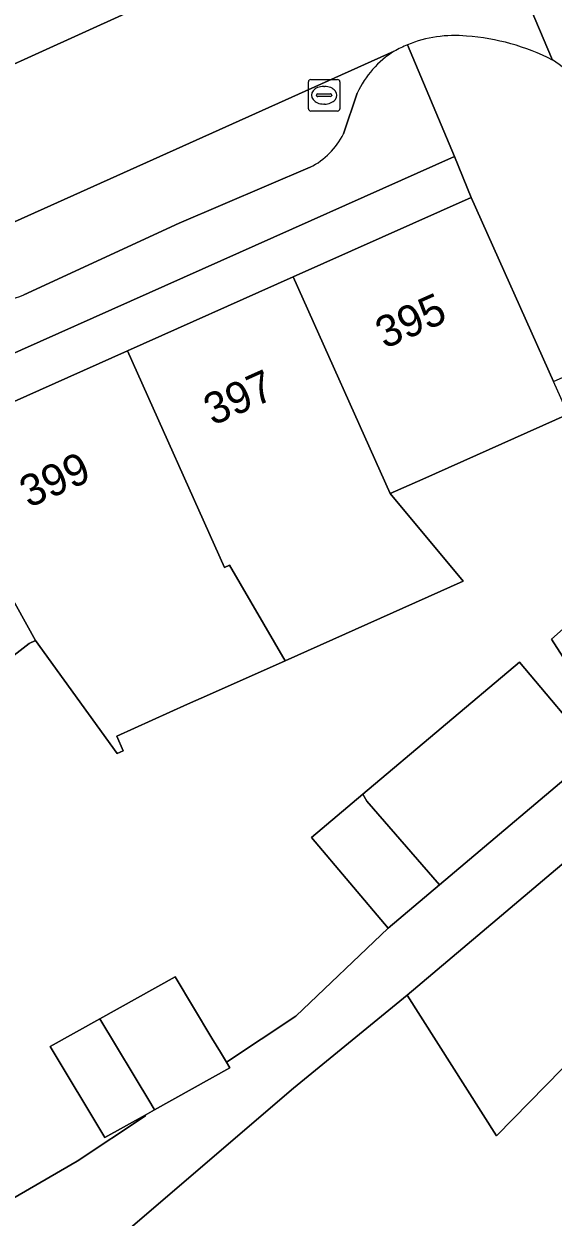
# Model space of a CAD drawing. Extents: x 159217 to 160349, y 381246 to 382172.
# Drawn here: x 159935.86 to 159952.63, y 381548.06 to 381585.9 of the extents above; entities that cross this region are included whole.
import ezdxf

# ---------------------------------------------------------------- set-up
doc = ezdxf.new("R2010")
doc.units = 0
for name, color, linetype in [('IMGEO_Erf', 7, 'Continuous'), ('IMGEO_Kolk', 7, 'Continuous'), ('IMGEO_Pand', 7, 'Continuous'), ('IMGEO_Pand_nummerreeks', 7, 'Continuous'), ('IMGEO_Parkeervlak_open', 7, 'Continuous'), ('IMGEO_Rijbaan_lokaal_open', 7, 'Continuous'), ('IMGEO_Voetpad_open', 7, 'Continuous')]:
    doc.layers.add(name, color=color, linetype=linetype)

msp = doc.modelspace()

# ---------------------------------------------------------------- linework, layer by layer
at = {"layer": 'IMGEO_Erf'}
msp.add_lwpolyline([(159917.626, 381561.413), (159922.162, 381564.929), (159926.698, 381568.444), (159931.35, 381572.05), (159932.725, 381572.665), (159934.053, 381573.258), (159939.145, 381575.534), (159944.394, 381577.88), (159950.038, 381580.402), (159949.504, 381581.701), (159933.502, 381574.549), (159930.356, 381573.305), (159889.378, 381541.471), (159890.288, 381540.224), (159894.945, 381543.834), (159899.482, 381547.35), (159903.996, 381550.849), (159908.553, 381554.381), (159913.09, 381557.897)], close=True, dxfattribs=at)
for points in [[(159953.11, 381573.529), (159948.501, 381571.469), (159947.464, 381571.008), (159949.781, 381568.226), (159944.139, 381565.707), (159941.738, 381564.635), (159941.047, 381564.326), (159938.802, 381563.312), (159939.007, 381562.852), (159938.819, 381562.762), (159936.225, 381566.345), (159936.027, 381566.257), (159931.263, 381562.556), (159933.07, 381560.437), (159928.246, 381556.689), (159926.731, 381559.035), (159924.542, 381557.335), (159927.222, 381553.885), (159924.408, 381551.699), (159922.395, 381550.547), (159919.914, 381553.74), (159917.666, 381551.993), (159913.134, 381548.473), (159915.28, 381545.267)], [(159954.556, 381563.311), (159952.585, 381566.39), (159957.352, 381570.628)], [(159934.06, 381547.814), (159937.546, 381549.84), (159939.717, 381551.28), (159939.706, 381551.301), (159938.424, 381550.586), (159936.691, 381553.469), (159938.267, 381554.349), (159940.655, 381555.682), (159941.821, 381553.742), (159942.09, 381553.294), (159942.279, 381552.98), (159944.478, 381554.439), (159947.402, 381557.226), (159944.975, 381560.098), (159946.603, 381561.473), (159951.562, 381565.663), (159953.989, 381562.791)], [(159952.92, 381552.768), (159950.834, 381550.644), (159948.011, 381555.101), (159944.404, 381552.153), (159937.02, 381545.819), (159940.421, 381541.327), (159940.685, 381541.532), (159938.589, 381544.23), (159940.733, 381545.896), (159942.829, 381543.198), (159942.422, 381542.882), (159951.3, 381531.456), (159943.138, 381544.018), (159944.255, 381544.797), (159946.817, 381546.584), (159948.314, 381544.437), (159945.752, 381542.65), (159947.286, 381539.908), (159949.901, 381541.712), (159952.05, 381538.597), (159953.571, 381536.391), (159950.955, 381534.587), (159952.061, 381532.983), (159961.824, 381539.096)]]:
    msp.add_lwpolyline(points, dxfattribs=at)
at = {"layer": 'IMGEO_Kolk'}
for p, q in [((159944.875, 381583.213), (159944.875, 381584.065)), ((159944.95, 381584.139), (159945.802, 381584.139)), ((159945.876, 381584.065), (159945.876, 381583.213)), ((159945.363, 381583.919), (159945.388, 381583.919)), ((159945.134, 381583.633), (159945.134, 381583.645)), ((159945.572, 381583.596), (159945.174, 381583.596)), ((159945.177, 381583.682), (159945.575, 381583.682)), ((159945.386, 381583.359), (159945.361, 381583.359)), ((159945.618, 381583.645), (159945.618, 381583.633)), ((159945.802, 381583.139), (159944.95, 381583.139))]:
    msp.add_line(p, q, dxfattribs=at)
for points in [[(159944.875, 381583.213), (159944.875, 381584.065)], [(159944.95, 381584.139), (159945.802, 381584.139)], [(159945.876, 381584.065), (159945.876, 381583.213)], [(159945.802, 381583.139), (159944.95, 381583.139)]]:
    msp.add_lwpolyline(points, dxfattribs=at)
for centre, radius, start, end in [((159944.952, 381584.063), 0.0765, 91.552, 178.448), ((159944.952, 381584.063), 0.0765, 91.552, 178.448), ((159945.8, 381584.063), 0.0765, 1.552, 88.448), ((159945.8, 381584.063), 0.0765, 1.552, 88.448), ((159945.174, 381583.642), 0.0403, 85.8775, 175.7526), ((159945.171, 381583.632), 0.0366, 178.938, 274.7102), ((159945.575, 381583.639), 0.043, 264.8664, 352.4533), ((159945.579, 381583.644), 0.0386, 1.7309, 96.639), ((159944.952, 381583.215), 0.0765, 181.552, 268.448), ((159944.952, 381583.215), 0.0765, 181.552, 268.448), ((159945.8, 381583.215), 0.0765, 271.552, 358.448), ((159945.8, 381583.215), 0.0765, 271.552, 358.448)]:
    msp.add_arc(centre, radius, start, end, dxfattribs=at)
for centre, major_axis, ratio, start_param, end_param in [((159945.362, 381583.639), (-0.387, 0.002), 0.722429, 4.712389, 7.853982), ((159945.387, 381583.639), (-0.39, 0.002), 0.717154, 1.570796, 4.712389)]:
    msp.add_ellipse(centre, major_axis=major_axis, ratio=ratio, start_param=start_param, end_param=end_param, dxfattribs=at)
at = {"layer": 'IMGEO_Pand'}
for points in [[(159944.394, 381577.88), (159947.464, 381571.008), (159948.501, 381571.469), (159953.11, 381573.529), (159952.649, 381574.56), (159950.038, 381580.402)], [(159944.394, 381577.88), (159939.145, 381575.534), (159942.215, 381568.662), (159942.376, 381568.734), (159944.139, 381565.707), (159949.781, 381568.226), (159947.464, 381571.008)], [(159939.145, 381575.534), (159934.053, 381573.258), (159932.725, 381572.665), (159936.225, 381566.345), (159938.819, 381562.762), (159939.007, 381562.852), (159938.802, 381563.312), (159941.047, 381564.326), (159941.738, 381564.635), (159944.139, 381565.707), (159942.376, 381568.734), (159942.215, 381568.662)], [(159936.225, 381566.345), (159932.725, 381572.665), (159931.35, 381572.05), (159926.698, 381568.444), (159931.263, 381562.556), (159936.027, 381566.257)], [(159959.471, 381567.318), (159957.352, 381570.628), (159952.585, 381566.39), (159954.556, 381563.311), (159954.704, 381563.08)], [(159946.603, 381561.473), (159946.731, 381561.254), (159949.035, 381558.605), (159953.989, 381562.791), (159951.562, 381565.663)], [(159963.233, 381559.251), (159960.285, 381563.94), (159956.053, 381561.279), (159953.188, 381559.477), (159950.246, 381556.99), (159948.011, 381555.101), (159950.834, 381550.644), (159952.92, 381552.768), (159953.611, 381553.203)], [(159946.603, 381561.473), (159944.975, 381560.098), (159947.402, 381557.226), (159949.035, 381558.605), (159946.731, 381561.254)], [(159938.267, 381554.349), (159939.882, 381551.663), (159940.001, 381551.466), (159942.388, 381552.799), (159942.279, 381552.98), (159942.09, 381553.294), (159941.821, 381553.742), (159940.655, 381555.682)], [(159938.267, 381554.349), (159936.691, 381553.469), (159938.424, 381550.586), (159939.706, 381551.301), (159940.001, 381551.466), (159939.882, 381551.663)]]:
    msp.add_lwpolyline(points, close=True, dxfattribs=at)
at = {"layer": 'IMGEO_Parkeervlak_open'}
for points in [[(159928.429, 381581.4), (159942.971, 381588.011), (159944.35, 381588.666), (159945.766, 381589.401), (159946.041, 381589.576)], [(159947.598, 381585.035), (159932.52, 381578.264)], [(159945.989, 381582.414), (159946.427, 381583.706)], [(159935.86, 381577.308), (159940.778, 381579.578), (159944.935, 381581.358)]]:
    msp.add_lwpolyline(points, dxfattribs=at)
for centre, radius, start, end in [((159949.178, 381582.463), 3.019, 121.5547, 155.6779), ((159943.895, 381583.45), 2.336, 296.4293, 333.6793), ((159935.357, 381578.395), 1.198, 240.8396, 294.8402)]:
    msp.add_arc(centre, radius, start, end, dxfattribs=at)
at = {"layer": 'IMGEO_Rijbaan_lokaal_open'}
for points in [[(159948.993, 381593.309), (159952.616, 381584.757)], [(159952.616, 381584.757), (159948.993, 381593.309)], [(159946.041, 381589.576), (159945.766, 381589.401), (159944.35, 381588.666), (159942.971, 381588.011), (159928.429, 381581.4)], [(159932.52, 381578.264), (159947.598, 381585.035)]]:
    msp.add_lwpolyline(points, dxfattribs=at)
for centre, radius, start, end in [((159949.529, 381581.585), 3.954, 112.4611, 119.2449), ((159949.506, 381581.623), 3.91, 84.3537, 112.3604), ((159949.392, 381578.434), 7.097, 62.9822, 85.9674), ((159950.747, 381581.897), 3.417, 23.6782, 56.8359)]:
    msp.add_arc(centre, radius, start, end, dxfattribs=at)
at = {"layer": 'IMGEO_Voetpad_open'}
for points in [[(159949.504, 381581.701), (159948.019, 381585.239)], [(159948.019, 381585.239), (159949.504, 381581.701), (159950.038, 381580.402), (159952.649, 381574.56), (159954.349, 381575.319), (159957.352, 381570.628), (159959.471, 381567.318), (159961.234, 381564.542), (159972.947, 381546.097), (159973.736, 381544.855), (159975.35, 381542.289), (159976.968, 381539.715), (159980.016, 381534.943), (159983.501, 381529.306), (159985.588, 381526.009), (159985.706, 381525.704)], [(159946.427, 381583.706), (159945.989, 381582.414)], [(159860.517, 381507.905), (159864.787, 381512.841), (159865.974, 381514.42), (159869.802, 381519.033), (159876.008, 381526.514), (159879.711, 381530.976), (159883.341, 381535.352), (159887.093, 381539.873), (159889.378, 381541.471), (159930.356, 381573.305), (159933.502, 381574.549), (159949.504, 381581.701)], [(159944.935, 381581.358), (159940.778, 381579.578), (159935.86, 381577.308)], [(159953.989, 381562.791), (159949.035, 381558.605), (159947.402, 381557.226), (159944.478, 381554.439), (159942.279, 381552.98), (159942.388, 381552.799), (159940.001, 381551.466), (159939.706, 381551.301), (159939.717, 381551.28), (159937.546, 381549.84), (159934.06, 381547.814)], [(159894.582, 381506.306), (159906.433, 381515.461), (159910.859, 381518.811), (159914.722, 381521.734), (159921.558, 381526.935), (159921.578, 381526.911), (159922.835, 381527.906), (159926.153, 381530.534), (159930.569, 381534.032), (159930.743, 381533.808), (159940.421, 381541.327), (159937.02, 381545.819), (159944.404, 381552.153), (159948.011, 381555.101), (159950.246, 381556.99), (159953.188, 381559.477)]]:
    msp.add_lwpolyline(points, dxfattribs=at)
for centre, radius, start, end in [((159949.529, 381581.585), 3.954, 112.4611, 119.2449), ((159949.506, 381581.623), 3.91, 84.3537, 112.3604), ((159949.392, 381578.434), 7.097, 62.9822, 85.9674), ((159949.178, 381582.463), 3.019, 121.5547, 155.6779), ((159950.747, 381581.897), 3.417, 23.6782, 56.8359), ((159943.895, 381583.45), 2.336, 296.4293, 333.6793), ((159935.357, 381578.395), 1.198, 240.8396, 294.8402)]:
    msp.add_arc(centre, radius, start, end, dxfattribs=at)

# ---------------------------------------------------------------- texts
at = {"layer": 'IMGEO_Pand_nummerreeks'}
for s, p in [('395', (159947.296, 381575.583)), ('397', (159941.85, 381573.149)), ('399', (159936.016, 381570.542))]:
    msp.add_text(s, height=1, rotation=24.0807, dxfattribs=at).set_placement(p)

doc.saveas('drawing.dxf')
